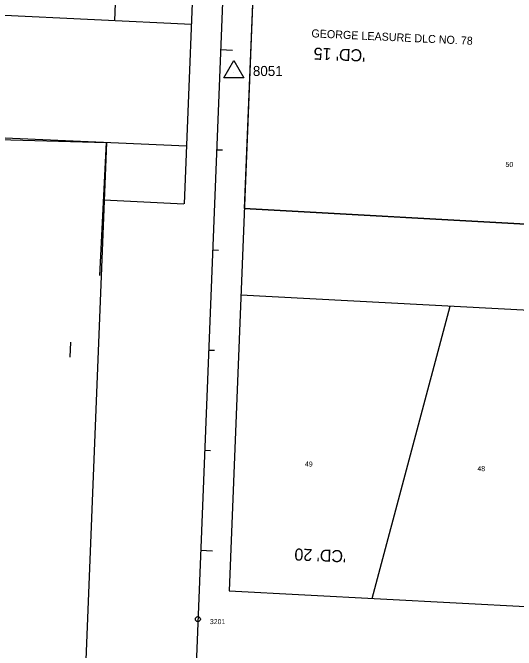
# Model space of a CAD drawing. Extents: x 7581380 to 7602708, y 543740 to 556109.
# Drawn here: x 7591226 to 7591728, y 549047 to 549683 of the extents above; entities that cross this region are included whole.
import ezdxf

# ---------------------------------------------------------------- set-up
doc = ezdxf.new("R2010")
doc.units = 0
for name, color, linetype in [('E_SURV_ALIGN_MinorTx', 7, 'Continuous'), ('E_SURV_BNDRY_CROW', 7, 'Continuous'), ('E_SURV_BNDRY_GovDLCLine', 7, 'Continuous'), ('E_SURV_BNDRY_GovDLCLineTx', 7, 'Continuous'), ('E_SURV_BNDRY_Property', 7, 'Continuous'), ('E_SURV_BNDRY_SubdivisionTx', 7, 'Continuous'), ('E_SURV_MON_FdMon', 7, 'Continuous'), ('E_SURV_MON_FdMonTx', 7, 'Continuous'), ('E_SURV_NTW_SetNtwPt', 7, 'Continuous'), ('E_SURV_NTW_SetNtwPtTx', 7, 'Continuous'), ('P_RW_FILE_AreaShapeFee', 7, 'Continuous'), ('P_RW_FILE_AreaShapeRemain', 7, 'Continuous')]:
    doc.layers.add(name, color=color, linetype=linetype)

msp = doc.modelspace()

# ---------------------------------------------------------------- linework, layer by layer
at = {"layer": 'E_SURV_ALIGN_MinorTx'}
for points in [[(7591445.12, 549645.07), (7591433.13, 549645.55)], [(7591435.16, 549545.39), (7591429.16, 549545.63)], [(7591431.18, 549445.47), (7591425.19, 549445.71)], [(7591427.21, 549345.55), (7591421.22, 549345.79)], [(7591423.24, 549245.63), (7591417.25, 549245.87)], [(7591425.26, 549145.47), (7591413.27, 549145.94)]]:
    msp.add_lwpolyline(points, dxfattribs=at)
at = {"layer": 'E_SURV_BNDRY_CROW'}
msp.add_line((7591312.91, 549420.48), (7591319.41, 549553.3), dxfattribs=at)
for points in [[(7591421.55, 550109.61), (7591397, 549491.91)], [(7591481.56, 550108.65), (7591441.7, 549105.87)]]:
    msp.add_lwpolyline(points, dxfattribs=at)
at = {"layer": 'E_SURV_BNDRY_GovDLCLine'}
msp.add_lwpolyline([(7591452.99, 550145.16), (7591385.11, 548437.45)], dxfattribs=at)
at = {"layer": 'E_SURV_BNDRY_Property'}
for p, q in [((7591404.12, 549670.93), (7591204.46, 549680.57)), ((7591199.64, 549558.62), (7591399.3, 549549.76)), ((7591316.59, 549495.84), (7591396.5, 549491.94)), ((7591773.7, 549469.66), (7591456.86, 549487.26)), ((7591584.48, 549098.25), (7591662.3, 549389.91)), ((7591441.7, 549105.87), (7593371.87, 549002.85))]:
    msp.add_line(p, q, dxfattribs=at)
for points in [[(7591332.14, 549797.56), (7591327.25, 549674.64)], [(7591453.44, 549401.07), (7593576.59, 549288.37)]]:
    msp.add_lwpolyline(points, dxfattribs=at)
at = {"layer": 'E_SURV_MON_FdMon'}
msp.add_circle((7591410.58, 549077.64), 2.5, dxfattribs=at)
at = {"layer": 'E_SURV_NTW_SetNtwPt'}
for p, q in [((7591436.58, 549617.55), (7591446.58, 549634.87)), ((7591446.58, 549634.87), (7591456.58, 549617.55)), ((7591446.58, 549623.32), (7591446.58, 549623.32)), ((7591456.58, 549617.55), (7591436.58, 549617.55))]:
    msp.add_line(p, q, dxfattribs=at)
at = {"layer": 'P_RW_FILE_AreaShapeFee'}
msp.add_line((7591283.45, 549353.86), (7591282.85, 549338.86), dxfattribs=at)
at = {"layer": 'P_RW_FILE_AreaShapeRemain'}
for points in [[(7590877.11, 549462.62), (7590903.23, 550131.64), (7590913.23, 550131.36), (7591127.83, 550118.26), (7591126.28, 550092.81), (7591135.26, 550092.26), (7591137.12, 550122.71), (7591221.78, 550118.54), (7591199.56, 549556.63), (7591319.41, 549553.3), (7591279.45, 548554.14)], [(7591792.99, 549939.34), (7591475.51, 549956.39), (7591465.97, 549716.25), (7591456.86, 549487.26), (7591773.7, 549469.66), (7591783.29, 549699.41), (7591930.21, 549691.61), (7591933.69, 549765.02)]]:
    msp.add_lwpolyline(points, dxfattribs=at)

# ---------------------------------------------------------------- texts
at = {"layer": 'E_SURV_ALIGN_MinorTx'}
for s, p in [("'CD' 15", (7591577.87, 549645.8)), ("'CD' 20", (7591558.76, 549146.17))]:
    msp.add_text(s, height=12, rotation=177.72377, dxfattribs=at).set_placement(p)
at = {"layer": 'E_SURV_BNDRY_GovDLCLineTx'}
msp.add_text('GEORGE LEASURE DLC NO. 78', height=8, rotation=357.29308, dxfattribs=at).set_placement((7591523.74, 549658.16))
at = {"layer": 'E_SURV_BNDRY_SubdivisionTx'}
for s, p in [('50', (7591717.54, 549528.83)), ('49', (7591517.37, 549230)), ('48', (7591689.42, 549225.38))]:
    msp.add_text(s, height=5, rotation=358.46152, dxfattribs=at).set_placement(p)
at = {"layer": 'E_SURV_MON_FdMonTx'}
msp.add_text('3201', height=5, dxfattribs=at).set_placement((7591422.58, 549072.64))
at = {"layer": 'E_SURV_NTW_SetNtwPtTx'}
msp.add_text('8051', height=10, dxfattribs=at).set_placement((7591465.47, 549619.51))

doc.saveas('drawing.dxf')
